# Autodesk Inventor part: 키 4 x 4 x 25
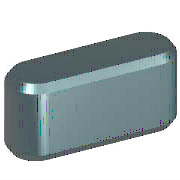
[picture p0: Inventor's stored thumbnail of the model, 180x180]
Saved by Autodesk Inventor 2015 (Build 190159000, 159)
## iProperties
IsCustomPart: 1
Created: 2012-02
Part Number: 키 4 x 4 x 25
Material: 강철, 연강
Description: 키 및 해당 키홈
Document SubType Name: Modeling
Standard: KS B 1311
Designer: mduedu
Standards Organization: KS
Language: ko-KR
Size Designation: 4 x 4 x 25
Categories: <MemberInstance><Categories><Category DisplayName="샤프트 부품" InternalName="7f7aeb1f-a693-4053-b835-cee3144e0d98" Mnemonic="SHFT"><Category DisplayName="키" Interna
Density: 7.85 g/cm^3
Appearance: 노란색
Mass: 3.00567 g
Surface Area: 3.95253 cm^2
Volume: 0.382888 cm^3
Author: mduedu
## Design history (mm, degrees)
workplane "Work Plane1"
workplane "Work Plane2"
sketch "스케치1"
  geometry: L1 (2, 2)-(23, 2); L2 (23, -2)-(2, -2); L3 (0, 9.4)-(0, -7.4) reference; L4 (-5, 0)-(30, 0) reference; L5 (25, 0)-(25, 7); A1 r 2 centre (2, 0) between (2, 2) and (2, -2); A2 r 2 centre (23, 0) between (23, -2) and (23, 2)
  constraints: 6 end point, 5 point on circle, 4 tangent, 3 point on line, 2 centre point, 1 horizontal, 1 parallel, 1 perpendicular
  dimensions: "d0" = 2 radius of A1 (= 0.5 x PB); "d13" = 2 radius of A2 (= 0.5 x PB); "d14" = 25 distance between parallel lines of L5 L3 (= NLG)
extrude "본체1" new body sketch "스케치1" taper "d3" = 0 deg; stored distance "d4" = 10
workplane "Work Plane3"
body "Solid1"
chamfer "모따기1" distance "d8" = 0.25 (= PHH); stored, may be unused: second distance "d9" = 0.25 (= PHH), angle "d15" = 45 deg
other parameters: "d1" = -2.5 (= -PNT), "d2" = 1.5 (= PH - PNT), "NLG" = 25 [user parameter; used in 3 equation terms], "PB" = 4 [user parameter; used in 2 equation terms], "PNT" = 2.5 [user parameter; used in 2 equation terms], "PH" = 4 [user parameter; used in 1 equation term], "PHH" = 0.25 [user parameter; used in 2 equation terms], "d10" = 0, "d16" = 0, "d17" = 0, "d18" = 0, "PLB2" = 25 (= NLG) [user parameter], "WDMAX" = 12 [user parameter], "PLB1" = 25 (= NLG) [user parameter], "RR" = 0.08 [user parameter], "PUEB" = 1.8 [user parameter]
